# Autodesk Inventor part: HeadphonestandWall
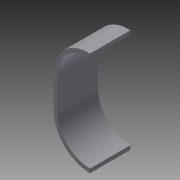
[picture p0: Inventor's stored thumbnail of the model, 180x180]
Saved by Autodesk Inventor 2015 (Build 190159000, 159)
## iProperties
Created: 2016-07
Part Number: HeadphonestandWall
Material: Generisch
Document SubType Name: Modeling
Designer: pichl
Density: 1 g/cm^3
Appearance: Vorgabe
Author: pichl
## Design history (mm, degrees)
sketch "Skizze1"
  geometry: L1 (45.022, -62.701)-(45.022, -82.701); L2 (45.022, -62.701)-(45.022, -42.701); L3 (40.022, -42.701)-(40.022, -65); L4 (40.022, -65)-(40.022, -82.701); L5 (0, 0)-(0, -5.008); L6 (0, -123.062)-(0, -128.062); A1 r 42.761 centre (2.261, -42.701) between (45.022, -42.701) and (0, 0); A2 r 45.362 centre (-0.34, -82.701) between (0, -128.062) and (45.022, -82.701); A3 r 37.761 centre (2.261, -42.701) between (40.022, -42.701) and (0, -5.008); A4 r 40.362 centre (-0.34, -82.701) between (0, -123.062) and (40.022, -82.701); 1 further point
  constraints: 12 end point, 8 point on circle, 4 centre point, 4 vertical, 2 tangent, 1 coincident, 3 other
  dimensions: "d0" = 20 distance of L1.start L1.end; "d1" = 20 distance of L1.start L2.end; "d2" = 5 radial gap between concentric circles of A1 A3
extrude "Extrusion1" new body sketch "Skizze1" distance "d3" = 50; taper "d4" = 0 deg
sketch "Skizze2"
  geometry: L1 (-45.022, 82.701)-(-45.022, 42.701) reference; L2 (-45.022, 57.701)-(-45.022, 67.701); C1 r 1 at (-47.5, 62.701); A1 r 5 centre (-45.022, 62.701) between (-45.022, 67.701) and (-45.022, 57.701); 4 further points
  constraints: 2 centre point, 2 coincident, 2 end point, 2 point on circle, 2 point on line, 1 collinear, 1 midpoint
  dimensions: "d5" = 10 diameter of A1; "d6" = 2 diameter of C1
extrude "Extrusion2" join sketch "Skizze2" distance "d7" = 3; taper "d8" = 0 deg
node "Volumenkörper1"
